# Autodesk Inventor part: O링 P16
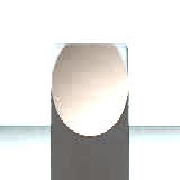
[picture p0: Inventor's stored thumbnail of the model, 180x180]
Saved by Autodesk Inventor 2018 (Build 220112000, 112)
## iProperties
IsCustomPart: 1
Created: 2012-02
Part Number: O링 P16
Material: 고무
Description: O-링
Document SubType Name: Modeling
Standard: JIS 2406
Designer: mdu-01
Standards Organization: JIS
Language: ko-KR
Size Designation: P16
Categories: <MemberInstance><Categories><Category DisplayName="샤프트 부품" InternalName="7f7aeb1f-a693-4053-b835-cee3144e0d98" Mnemonic="SHFT"><Category DisplayName="실링" Intern
Density: 0.93 g/cm^3
Appearance: 고무 - 검은색 - 버전 1.1
Author: mdu-01
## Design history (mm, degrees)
revolve "본체" stored, may be unused: angle "d19" = 90 deg
body "Solid1"
sketch "스케치1"
  geometry: L1 (-0.011, 0)-(-0.011, 0); L2 (-0.663, 2)-(0.663, 2); L3 (-0.663, 0)-(0.663, 0); L4 (-4, -8)-(6.034, -8); L5 (-6.007, 0)-(8.04, 0) reference; L6 (0, 4.64)-(0, -12.44) reference; A1 r 1.2 centre (0, 1) between (-0.663, 2) and (-0.663, 0); A2 r 1.2 centre (0, 1) between (0.663, 0) and (0.663, 2)
  constraints: 8 end point, 4 point on circle, 2 centre point, 2 horizontal alignment, 2 parallel, 1 coincident, 1 horizontal, 1 point on line, 1 other
  dimensions: "d0" = 16 diameter of L5 L4 (= NND); "d1" = 1 distance from line of A1.centre L2 (= -0.25 x NND + 0.25 x NDOR); "d2" = 1.2 radius of A1 (= 0.5 x QDM); "d3" = 1 distance from line of L3 A1.centre (= -0.25 x NND + 0.25 x NDOR); "d4" = 2 distance between parallel lines of L5 L2 (= -0.5 x NND + 0.5 x NDOR)
other parameters: "QDM" = 2.4 [user parameter; used in 1 equation term], "NND" = 16 [user parameter; used in 5 equation terms], "d5" = 0, "d36" = 0, "R2" = 0.2 [user parameter], "NB3" = 6 [user parameter], "SD1" = 15.8 [user parameter], "R1" = 0.4 [user parameter], "NB2" = 4.4 [user parameter], "NB1" = 3.2 [user parameter], "BD" = 16.14 [user parameter], "NTOR" = 2 (= -0.5 x NND + 0.5 x NDOR) [user parameter]
